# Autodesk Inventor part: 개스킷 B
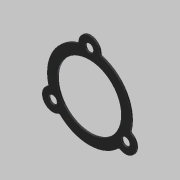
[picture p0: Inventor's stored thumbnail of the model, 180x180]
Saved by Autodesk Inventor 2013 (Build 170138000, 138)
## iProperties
Created: 2020-03
Part Number: 개스킷 B
Material: 고무
Document SubType Name: Modeling
Designer: mduedu
Density: 1 g/cm^3
Author: mduedu
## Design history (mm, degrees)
sketch "스케치1" dims "d1" = 55
  geometry: C1 r 21 at (0, 0); C2 r 7 at (0, 27.5); C3 r 7 at (-23.816, -13.75); C4 r 7 at (23.816, -13.75); 2 further points
  constraints: 4 centre point, 2 coincident, 2 vertical alignment, 9 other
  dimensions: "d0" = 42 diameter of C1; "d2" = 14 diameter of C2; "d5" = 360 deg dimension on point (0, 0) C2.centre (derived)
extrude "돌출1" new body sketch "스케치1" distance "d7" = 1; taper "d8" = 0 deg
extrude "돌출2" cut sketch "스케치1" stored distance "d9" = 1; taper "d10" = 0 deg
fillet "모깎기1" dims "d11" = 1
sketch "스케치2"
  geometry: C1 r 21 at (0, 0) reference; A1 r 7 centre (0, 27.5) between (6.999, 27.373) and (-6.999, 27.373) reference; A2 r 27.5 centre (0, 0) between (26.718, -6.513) and (7.718, 26.395) reference; A3 r 1 centre (7.999, 27.355) between (6.999, 27.373) and (7.718, 26.395) reference; A4 r 7 centre (0, 27.5) between (6.999, 27.373) and (-6.999, 27.373) reference; A5 r 1 centre (-7.999, 27.355) between (-7.718, 26.395) and (-6.999, 27.373) reference; A6 r 27.5 centre (0, 0) between (-7.718, 26.395) and (-26.718, -6.513) reference; A7 r 1 centre (-27.689, -6.75) between (-27.205, -7.625) and (-26.718, -6.513) reference; A8 r 7 centre (-23.816, -13.75) between (-27.205, -7.625) and (-20.206, -19.748) reference; A9 r 1 centre (-19.69, -20.604) between (-19, -19.881) and (-20.206, -19.748) reference; A10 r 27.5 centre (0, 0) between (-19, -19.881) and (19, -19.881) reference; A11 r 1 centre (19.69, -20.604) between (20.206, -19.748) and (19, -19.881) reference; A12 r 7 centre (23.816, -13.75) between (20.206, -19.748) and (27.205, -7.625) reference; A13 r 1 centre (27.689, -6.75) between (26.718, -6.513) and (27.205, -7.625) reference; 4 further points
  constraints: 3 coincident
hole "구멍1" sketch "스케치2" at (0, 27.5), (23.816, -13.75), (-23.816, -13.75) diameter "d12" = 5.5; stored, may be unused: countersink angle "d16" = 90 deg, drill point angle "d18" = 118 deg; dims "d13" = 6, "d14" = 4, "d15" = 2, "d17" = 8
node "솔리드1"
node "투영된 루프1"
